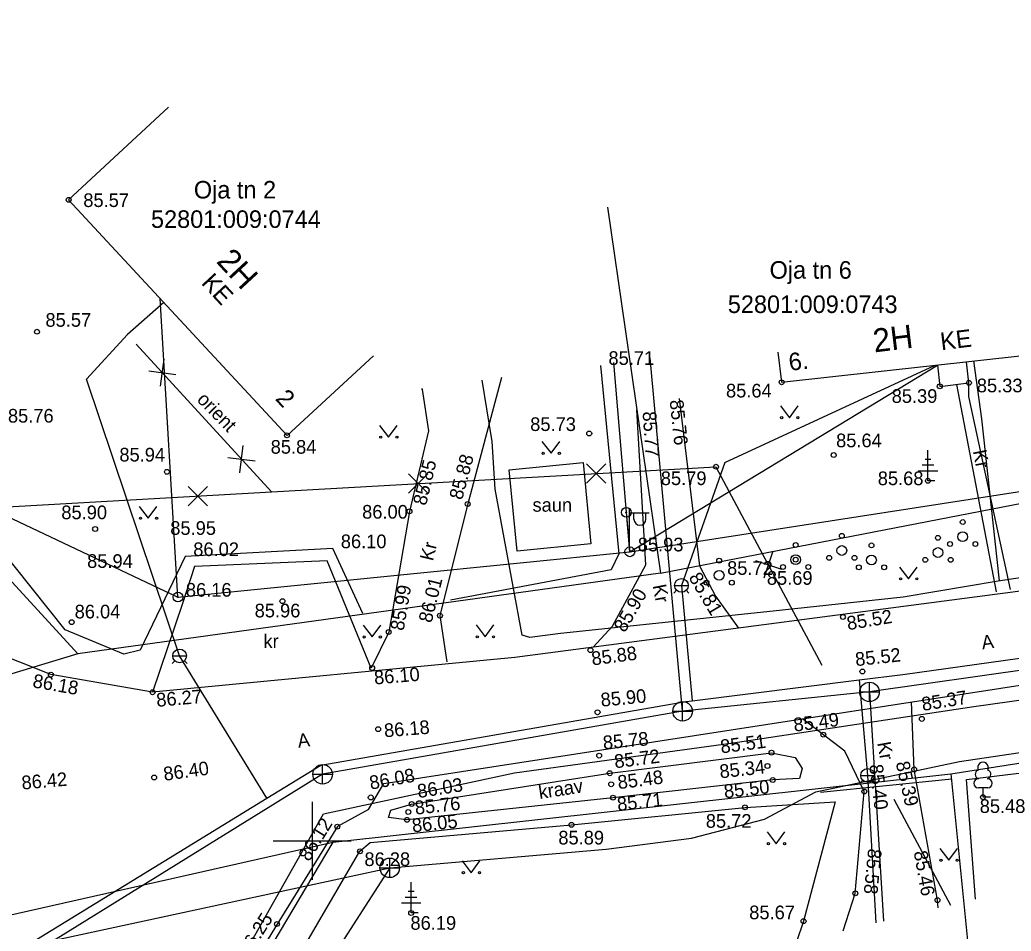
# Model space of a CAD drawing. Extents: x 648748 to 649126, y 6457789 to 6458252.
# Drawn here: x 648985 to 649035.8, y 6458145.4 to 6458192.1 of the extents above; entities that cross this region are included whole.
import ezdxf

# ---------------------------------------------------------------- set-up
doc = ezdxf.new("R2010")
doc.units = 0
for name, color, linetype in [('DTRASS', 7, 'Continuous'), ('HALJASTUS', 7, 'Continuous'), ('HOONE', 7, 'Continuous'), ('KKAEV', 7, 'Continuous'), ('KORGUS-EH2000', 7, 'Continuous'), ('KTRASS', 7, 'Continuous'), ('MPOHULIIN', 7, 'Continuous'), ('PIIR', 7, 'Continuous'), ('POST', 7, 'Continuous'), ('PUU', 7, 'Continuous'), ('RAJATIS', 7, 'Continuous'), ('SITRASS', 7, 'Continuous'), ('SKKAEV', 7, 'Continuous'), ('SKTRASS', 7, 'Continuous'), ('TEE', 7, 'Continuous'), ('VEEKOGU', 7, 'Continuous'), ('VKAEV', 7, 'Continuous'), ('VORK', 7, 'Continuous'), ('VTRASS', 7, 'Continuous')]:
    doc.layers.add(name, color=color, linetype=linetype)

msp = doc.modelspace()

# ---------------------------------------------------------------- linework, layer by layer
at = {"layer": 'DTRASS'}
msp.add_line((649026.058, 6458152.495), (649032.785, 6458153.165), dxfattribs=at)
at = {"layer": 'HALJASTUS'}
for p, q in [((649024, 6458172.292), (649024.463, 6458171.685)), ((649024.463, 6458171.685), (649024.909, 6458172.292)), ((649003.448, 6458171.291), (649003.911, 6458170.684)), ((649003.911, 6458170.684), (649004.357, 6458171.291)), ((649011.774, 6458170.467), (649012.237, 6458169.861)), ((649012.237, 6458169.861), (649012.683, 6458170.467)), ((648991.13, 6458167.138), (648991.594, 6458166.531)), ((648991.594, 6458166.531), (648992.039, 6458167.138)), ((649030.094, 6458164.031), (649030.558, 6458163.425)), ((649030.558, 6458163.425), (649031.003, 6458164.031)), ((649002.601, 6458161.053), (649003.064, 6458160.447)), ((649003.064, 6458160.447), (649003.51, 6458161.053)), ((649008.398, 6458161.061), (649008.861, 6458160.455)), ((649008.861, 6458160.455), (649009.307, 6458161.061)), ((649023.317, 6458150.454), (649023.781, 6458149.847)), ((649023.781, 6458149.847), (649024.226, 6458150.454)), ((649032.163, 6458149.605), (649032.627, 6458148.999)), ((649032.627, 6458148.999), (649033.072, 6458149.605)), ((649007.684, 6458148.969), (649008.147, 6458148.362)), ((649008.147, 6458148.362), (649008.593, 6458148.969))]:
    msp.add_line(p, q, dxfattribs=at)
for points in [[(649033.987, 6458147.007), (649033.538, 6458153.135), (649043.314, 6458154.31), (649049.482, 6458155.214)], [(648996.956, 6458140.042), (649002.443, 6458149.457), (649002.965, 6458149.902), (649013.289, 6458150.815), (649022.182, 6458151.711), (649026.81, 6458151.999), (649025.182, 6458145.874), (649024.817, 6458144.814)]]:
    msp.add_lwpolyline(points, dxfattribs=at)
for centre in [(649024.062, 6458171.685), (649024.891, 6458171.685), (649003.51, 6458170.684), (649004.339, 6458170.684), (649011.836, 6458169.861), (649012.665, 6458169.861), (648991.193, 6458166.531), (648992.022, 6458166.531), (649030.157, 6458163.425), (649030.986, 6458163.425), (649002.663, 6458160.447), (649003.492, 6458160.447), (649008.46, 6458160.455), (649009.289, 6458160.455), (649023.38, 6458149.847), (649024.209, 6458149.847), (649032.226, 6458148.999), (649033.055, 6458148.999), (649007.746, 6458148.362), (649008.575, 6458148.362)]:
    msp.add_circle(centre, 0.055, dxfattribs=at)
at = {"layer": 'HOONE'}
for points in [[(648992.634, 6458187.599), (648987.514, 6458182.852), (648998.705, 6458170.78), (649003.141, 6458174.853)], [(649023.87, 6458175.039), (649024.058, 6458173.502), (649041.542, 6458175.437), (649040.739, 6458182.695)], [(649032.042, 6458174.386), (649032.163, 6458173.293), (649033.658, 6458173.473), (649033.539, 6458174.551)]]:
    msp.add_lwpolyline(points, dxfattribs=at)
at = {"layer": 'KKAEV'}
for p, q in [((649028.562, 6458157.125), (649028.562, 6458158.125)), ((649028.062, 6458157.625), (649029.062, 6458157.625)), ((649018.983, 6458156.135), (649018.983, 6458157.135)), ((649018.483, 6458156.635), (649019.483, 6458156.635)), ((649000.53, 6458152.906), (649000.53, 6458153.906)), ((649000.03, 6458153.406), (649001.03, 6458153.406))]:
    msp.add_line(p, q, dxfattribs=at)
for centre in [(649028.562, 6458157.625), (649018.983, 6458156.635), (649000.53, 6458153.406)]:
    msp.add_circle(centre, 0.5, dxfattribs=at)
at = {"layer": 'KORGUS-EH2000'}
for centre in [(648987.514, 6458182.852), (648985.889, 6458176.092), (649024.058, 6458173.502), (649032.163, 6458173.293), (649033.658, 6458173.473), (648998.705, 6458170.78), (649014.196, 6458170.877), (649026.725, 6458169.771), (649020.691, 6458169.172), (648992.551, 6458168.912), (649031.556, 6458168.447), (649007.969, 6458167.262), (649004.981, 6458166.883), (648988.869, 6458165.982), (649024.777, 6458164.408), (648998.471, 6458162.282), (649006.543, 6458161.54), (649027.199, 6458161.469), (648987.666, 6458161.205), (649003.917, 6458160.7), (649014.257, 6458159.769), (649003.068, 6458158.855), (648986.6, 6458158.516), (649028.198, 6458158.673), (648991.816, 6458157.612), (649014.623, 6458156.586), (649031.244, 6458156.245), (649003.379, 6458155.722), (649026.193, 6458155.438), (649014.705, 6458154.364), (649023.539, 6458154.512), (649023.335, 6458153.829), (648991.897, 6458153.244), (649015.247, 6458153.46), (649030.851, 6458153.655), (649015.32, 6458152.895), (649023.601, 6458153.116), (649002.998, 6458152.22), (649015.413, 6458152.205), (649028.295, 6458152.521), (649034.38, 6458152.229), (649005.094, 6458151.881), (649022.182, 6458151.711), (649004.921, 6458151.471), (649001.287, 6458150.721), (649004.855, 6458151.069), (649013.289, 6458150.815), (649002.443, 6458149.457), (649027.835, 6458147.302), (649032.048, 6458146.955), (649005.068, 6458146.297), (648998.193, 6458145.731), (649025.182, 6458145.874)]:
    msp.add_circle(centre, 0.125, dxfattribs=at)
at = {"layer": 'KTRASS'}
for p, q in [((649018.983, 6458156.635), (649017.319, 6458174.757)), ((649061.979, 6458162.436), (649028.562, 6458157.625)), ((649028.562, 6458157.625), (649018.983, 6458156.635)), ((649028.562, 6458157.625), (649029.287, 6458145.883)), ((649018.983, 6458156.635), (649000.53, 6458153.406)), ((649000.53, 6458153.406), (648975.244, 6458137.772))]:
    msp.add_line(p, q, dxfattribs=at)
at = {"layer": 'MPOHULIIN'}
for p, q in [((648993.115, 6458162.488), (648992.205, 6458177.791)), ((649016.276, 6458164.81), (649015.453, 6458174.508)), ((649016.276, 6458164.81), (649032.042, 6458174.386))]:
    msp.add_line(p, q, dxfattribs=at)
msp.add_lwpolyline([(648949.064, 6458178.85), (648980.689, 6458168.372), (648993.115, 6458162.488), (649016.276, 6458164.81), (649054.033, 6458170.656), (649094.361, 6458177.194), (649107.677, 6458175.236)], dxfattribs=at)
at = {"layer": 'PIIR'}
for p, q in [((648955.09, 6458195.42), (648987.99, 6458159.58)), ((649015.133, 6458182.478), (649017.85, 6458163.71)), ((649017.85, 6458163.71), (649052.92, 6458170.51)), ((649017.85, 6458163.71), (648987.99, 6458159.58)), ((649032.73, 6458153.43), (649096.35, 6458163.48)), ((648987.99, 6458159.58), (648945.9, 6458146.87)), ((649001.06, 6458149.93), (649032.73, 6458153.43)), ((649032.73, 6458153.43), (649034.45, 6458136.158)), ((648970.31, 6458142.98), (649001.06, 6458149.93)), ((649001.06, 6458149.93), (648978.12, 6458111.43))]:
    msp.add_line(p, q, dxfattribs=at)
at = {"layer": 'POST'}
for p, q in [((649016.263, 6458165.052), (649016.263, 6458167.052)), ((649016.097, 6458166.83), (649016.276, 6458164.81)), ((649016.263, 6458166.802), (649017.263, 6458166.802)), ((649016.49, 6458166.481), (649016.49, 6458166.802)), ((649017.103, 6458166.481), (649017.103, 6458166.802))]:
    msp.add_line(p, q, dxfattribs=at)
for centre, radius in [((649016.097, 6458166.83), 0.25), ((649016.097, 6458166.83), 0.0234), ((649016.276, 6458164.81), 0.25), ((649016.276, 6458164.81), 0.0234), ((648993.115, 6458162.488), 0.25), ((648993.115, 6458162.488), 0.0234)]:
    msp.add_circle(centre, radius, dxfattribs=at)
msp.add_arc((649016.796, 6458166.481), 0.306, 180, 0, dxfattribs=at)
at = {"layer": 'PUU'}
for p, q in [((649031.556, 6458168.447), (649031.556, 6458170.022)), ((649031.856, 6458169.248), (649031.256, 6458169.248)), ((649031.706, 6458169.548), (649031.406, 6458169.548)), ((649032.056, 6458168.947), (649031.056, 6458168.947)), ((649031.916, 6458168.447), (649031.556, 6458168.447)), ((649034.62, 6458152.704), (649034.14, 6458152.704)), ((649034.38, 6458152.229), (649034.38, 6458152.704)), ((649034.76, 6458152.229), (649034.38, 6458152.229)), ((649005.068, 6458146.297), (649005.068, 6458147.872)), ((649005.218, 6458147.397), (649004.918, 6458147.397)), ((649005.568, 6458146.797), (649004.568, 6458146.797)), ((649005.368, 6458147.097), (649004.768, 6458147.097)), ((649005.428, 6458146.297), (649005.068, 6458146.297))]:
    msp.add_line(p, q, dxfattribs=at)
for points in [[(649014.775, 6458174.368), (649015.706, 6458164.701), (649015.321, 6458163.893), (649007.084, 6458162.33)], [(649002.59, 6458161.656), (649001.056, 6458164.973), (648993.494, 6458164.57), (648991.171, 6458159.775), (648990.345, 6458159.559), (648987.328, 6458160.816), (648981.354, 6458168.296)]]:
    msp.add_lwpolyline(points, dxfattribs=at)
for centre, radius in [((649033.34, 6458166.336), 0.125), ((649027.141, 6458165.628), 0.125), ((649032.069, 6458165.525), 0.125), ((649033.34, 6458165.586), 0.25), ((649024.777, 6458165.158), 0.125), ((649027.141, 6458164.878), 0.25), ((649028.663, 6458165.139), 0.125), ((649032.069, 6458164.775), 0.25), ((649032.69, 6458165.211), 0.125), ((649033.99, 6458165.211), 0.125), ((649020.855, 6458164.355), 0.125), ((649024.777, 6458164.408), 0.25), ((649026.491, 6458164.503), 0.125), ((649027.791, 6458164.503), 0.125), ((649028.663, 6458164.389), 0.25), ((649031.419, 6458164.4), 0.125), ((649032.719, 6458164.4), 0.125), ((649024.127, 6458164.033), 0.125), ((649025.427, 6458164.033), 0.125), ((649028.013, 6458164.014), 0.125), ((649029.313, 6458164.014), 0.125), ((649020.855, 6458163.605), 0.25), ((649020.205, 6458163.23), 0.125), ((649021.505, 6458163.23), 0.125)]:
    msp.add_circle(centre, radius, dxfattribs=at)
for centre, radius, start, end in [((649034.38, 6458153.749), 0.277, 332.58, 207.42), ((649034.209, 6458153.402), 0.233, 109.022, 253.142), ((649034.55, 6458153.402), 0.233, 286.851, 70.986), ((649034.142, 6458152.942), 0.238, 90.002, 269.395), ((649034.617, 6458152.942), 0.238, 270.605, 89.998)]:
    msp.add_arc(centre, radius, start, end, dxfattribs=at)
at = {"layer": 'RAJATIS'}
msp.add_lwpolyline([(649013.879, 6458169.385), (649014.284, 6458165.219), (649010.503, 6458164.851), (649010.098, 6458169.017), (649013.879, 6458169.385)], dxfattribs=at)
at = {"layer": 'SITRASS'}
for points in [[(649033.891, 6458174.596), (649034.294, 6458171.62), (649035.211, 6458163.32)], [(649050.779, 6458151.372), (649050.885, 6458151.848), (649050.846, 6458155.528), (649051.201, 6458159.4), (649049.722, 6458165.515), (649049.686, 6458165.487), (649035.158, 6458163.312), (649030.285, 6458162.491), (649023.632, 6458161.77), (649012.724, 6458160.616), (649011.154, 6458160.421), (649010.75, 6458160.531), (649009.382, 6458168.026), (649009.225, 6458170.467), (649008.715, 6458173.607)], [(648995.643, 6458121.195), (648992.459, 6458125.184), (648989.418, 6458128.665), (648988.834, 6458130.069), (648992.568, 6458137.175), (649000.571, 6458151.371), (649010.371, 6458153.481), (649021.569, 6458155.012), (649033.911, 6458156.878), (649048.154, 6458158.873), (649059.027, 6458160.391), (649071.774, 6458161.431), (649085.639, 6458163.321), (649085.929, 6458161.874)]]:
    msp.add_lwpolyline(points, dxfattribs=at)
at = {"layer": 'SKKAEV'}
for p, q in [((649003.97, 6458148.11), (649003.97, 6458149.11)), ((649003.47, 6458148.61), (649004.47, 6458148.61))]:
    msp.add_line(p, q, dxfattribs=at)
msp.add_circle((649003.97, 6458148.61), 0.5, dxfattribs=at)
at = {"layer": 'SKTRASS'}
for points in [[(649003.97, 6458148.61), (649015.069, 6458149.564), (649019.431, 6458150.139), (649023.183, 6458151.111), (649025.815, 6458152.505), (649033.168, 6458154.063), (649043.179, 6458155.542), (649052.834, 6458156.983), (649065.23, 6458159.005), (649081.287, 6458162.038), (649091.624, 6458163.937), (649099.708, 6458164.95)], [(648947.113, 6458135.218), (648950.496, 6458136.157), (648962.487, 6458139.467), (648972.91, 6458141.909), (649003.97, 6458148.61)], [(649003.97, 6458148.61), (648998.226, 6458139.651)]]:
    msp.add_lwpolyline(points, dxfattribs=at)
at = {"layer": 'TEE'}
for points in [[(649107.397, 6458177.046), (649100.717, 6458173.988), (649091.348, 6458171.54), (649080.638, 6458169.649), (649068.509, 6458167.394), (649058.16, 6458165.62), (649053.786, 6458164.971), (649038.247, 6458163.046), (649010.385, 6458159.395), (648991.816, 6458157.612), (648986.6, 6458158.516), (648983.403, 6458159.789), (648978.499, 6458164.674), (648956.171, 6458189.218), (648949.185, 6458196.386), (648941.448, 6458204.958), (648937.194, 6458209.825), (648934.521, 6458215.407), (648934.235, 6458222.731), (648937.629, 6458230.732), (648939.834, 6458235.213)], [(649009.706, 6458173.74), (649007.969, 6458167.262), (649006.543, 6458161.54), (649006.829, 6458159.623), (649006.897, 6458159.168)], [(649005.593, 6458173.19), (649005.638, 6458173.136), (649005.958, 6458171.01), (649004.981, 6458166.883), (649003.917, 6458160.7), (649003.021, 6458158.851)], [(649033.018, 6458173.396), (649035.056, 6458162.761)], [(649035.792, 6458162.882), (649033.645, 6458172.77), (649033.658, 6458173.473)], [(649018.812, 6458172.675), (649019.847, 6458164.09), (649020.662, 6458162.532), (649021.843, 6458160.896)], [(649002.881, 6458151.593), (649003.675, 6458152.941), (649070.906, 6458163.327), (649079.075, 6458164.441), (649081.585, 6458165.323), (649092.488, 6458167.317), (649101.716, 6458170.032), (649108.096, 6458172.531)], [(649014.395, 6458159.92), (649015.383, 6458161.002), (649017.103, 6458164.148), (649016.639, 6458172.09)], [(649003.021, 6458158.851), (649000.767, 6458164.354), (648993.963, 6458164.051), (648993.357, 6458162.163), (648991.816, 6458157.612)], [(649032.088, 6458146.553), (649032.048, 6458146.955), (649030.851, 6458153.655), (649030.715, 6458157.118)], [(649027.214, 6458145.388), (649027.835, 6458147.302), (649028.295, 6458152.521), (649027.289, 6458154.599), (649025.126, 6458156.255)], [(649002.881, 6458151.593), (649001.287, 6458150.721), (648998.193, 6458145.731), (648995.296, 6458140.982), (648997.086, 6458139.766), (648997.79, 6458139.425)]]:
    msp.add_lwpolyline(points, dxfattribs=at)
at = {"layer": 'VEEKOGU'}
msp.add_lwpolyline([(649005.094, 6458151.881), (649015.247, 6458153.46), (649023.539, 6458154.512), (649024.756, 6458154.263), (649025.118, 6458153.708), (649024.967, 6458153.185), (649023.601, 6458153.116), (649015.413, 6458152.205), (649004.855, 6458151.069), (649003.903, 6458151.188), (649004.033, 6458151.575), (649005.094, 6458151.881)], dxfattribs=at)
at = {"layer": 'VKAEV'}
for p, q in [((649018.571, 6458163.085), (649019.271, 6458163.085)), ((649018.674, 6458162.838), (649018.534, 6458162.698)), ((649019.169, 6458162.838), (649019.308, 6458162.698)), ((648992.849, 6458159.477), (648993.549, 6458159.477)), ((648992.952, 6458159.23), (648992.812, 6458159.09)), ((648993.447, 6458159.23), (648993.586, 6458159.09)), ((649028.113, 6458153.347), (649028.813, 6458153.347)), ((649028.216, 6458153.1), (649028.076, 6458152.96)), ((649028.711, 6458153.1), (649028.85, 6458152.96))]:
    msp.add_line(p, q, dxfattribs=at)
for centre in [(649018.921, 6458163.085), (648993.199, 6458159.477), (649028.463, 6458153.347)]:
    msp.add_circle(centre, 0.35, dxfattribs=at)
at = {"layer": 'VORK'}
for p, q in [((649000, 6458152), (649000, 6458148)), ((648998, 6458150), (649002, 6458150))]:
    msp.add_line(p, q, dxfattribs=at)
at = {"layer": 'VTRASS'}
for p, q in [((648992.225, 6458173.301), (648992.406, 6458174.69)), ((649021.144, 6458169.382), (649031.894, 6458174.369)), ((648991.621, 6458174.086), (648993.01, 6458173.905)), ((648996.281, 6458168.864), (648996.462, 6458170.253)), ((648995.678, 6458169.649), (648997.066, 6458169.468)), ((649014.057, 6458169.319), (649015.047, 6458168.329)), ((649014.057, 6458168.329), (649015.047, 6458169.319)), ((649020.691, 6458169.172), (649026.126, 6458159.007)), ((649004.941, 6458168.804), (649005.931, 6458167.814)), ((649004.941, 6458167.814), (649005.931, 6458168.804)), ((648993.639, 6458168.164), (648994.629, 6458167.174)), ((648993.639, 6458167.174), (648994.629, 6458168.164)), ((649023.159, 6458163.477), (649023.601, 6458164.806)), ((649022.716, 6458164.363), (649024.045, 6458163.921)), ((649029.8, 6458152.135), (649032.706, 6458146.701))]:
    msp.add_line(p, q, dxfattribs=at)
for points in [[(648904.231, 6458212.879), (648940.565, 6458193.977), (648965.109, 6458166.027), (648997.904, 6458167.882), (649020.691, 6458169.172)], [(648992.393, 6458177.589), (648990.522, 6458175.958)], [(648997.673, 6458152.175), (648993.199, 6458159.477), (648988.435, 6458173.654), (648990.522, 6458175.958)], [(648990.981, 6458175.456), (648997.904, 6458167.882)], [(649021.144, 6458169.382), (649018.921, 6458163.085), (649019.466, 6458157.178)], [(648976.302, 6458139.082), (648997.673, 6458152.175), (649000.44, 6458153.871), (649019.143, 6458157.138), (649019.466, 6458157.178), (649028.03, 6458158.241), (649030.273, 6458158.52), (649062.346, 6458163.005)], [(649028.03, 6458158.241), (649028.463, 6458153.347), (649028.886, 6458145.787)]]:
    msp.add_lwpolyline(points, dxfattribs=at)

# ---------------------------------------------------------------- texts
at = {"layer": 'HOONE'}
for s, height, rotation, p in [('2H', 1.2, 312.8319, (648995.038, 6458179.671)), ('KE', 0.9, 312.8319, (648994.273, 6458178.567)), ('2H', 1.2, 6.9664, (649028.812, 6458175.029)), ('KE', 0.9, 6.9664, (649032.244, 6458175.142)), ('6.', 0.9, 6.9664, (649024.473, 6458174.084)), ('2', 0.9, 312.8319, (648998.071, 6458172.63))]:
    msp.add_text(s, height=height, rotation=rotation, dxfattribs=at).set_placement(p)
at = {"layer": 'KORGUS-EH2000'}
for s, p in [('85.57', (648988.264, 6458182.486)), ('85.57', (648986.325, 6458176.347)), ('85.71', (649015.182, 6458174.391)), ('85.33', (649034.063, 6458172.987)), ('85.64', (649021.206, 6458172.722)), ('85.39', (649029.698, 6458172.446)), ('85.76', (648984.402, 6458171.434)), ('85.73', (649011.171, 6458171.004)), ('85.64', (649026.849, 6458170.17)), ('85.94', (648990.113, 6458169.44)), ('85.84', (648997.868, 6458169.84)), ('85.79', (649017.865, 6458168.231)), ('85.68', (649028.985, 6458168.228)), ('85.90', (648987.138, 6458166.483)), ('86.00', (649002.556, 6458166.511)), ('85.95', (648992.722, 6458165.68)), ('86.10', (649001.463, 6458164.996)), ('85.93', (649016.683, 6458164.833)), ('86.02', (648993.901, 6458164.593)), ('85.94', (648988.46, 6458163.986)), ('85.72', (649021.262, 6458163.628)), ('85.69', (649023.3, 6458163.12)), ('86.16', (648993.522, 6458162.511)), ('86.04', (648987.821, 6458161.397)), ('85.96', (648997.047, 6458161.449)), ('85.48', (649034.21, 6458151.423)), ('85.72', (649020.171, 6458150.664)), ('85.89', (649012.613, 6458149.808)), ('86.28', (649002.674, 6458148.704)), ('85.67', (649022.397, 6458145.975)), ('86.19', (649005.032, 6458145.436))]:
    msp.add_text(s, height=0.7, dxfattribs=at).set_placement(p)
for s, rotation, p in [('85.76', 276.0312, (649018.318, 6458172.572)), ('85.77', 274.0304, (649016.929, 6458171.988)), ('85.88', 74.9886, (649007.68, 6458167.436)), ('85.85', 76.6751, (649005.832, 6458167.15)), ('85.81', 300.5249, (649019.272, 6458163.498)), ('85.99', 80.2366, (649004.683, 6458160.735)), ('86.01', 76.0036, (649006.113, 6458161.133)), ('85.90', 60.1056, (649016.02, 6458160.632)), ('85.52', 9.3399, (649027.457, 6458160.793)), ('85.88', 7.4826, (649014.356, 6458158.983)), ('85.52', 6.1001, (649027.864, 6458158.947)), ('86.10', 4.6681, (649003.196, 6458158.01)), ('86.18', 350.1697, (648985.635, 6458157.869)), ('86.27', 4.8037, (648992.035, 6458156.863)), ('85.90', 5.3382, (649014.814, 6458156.87)), ('85.37', 9.2374, (649031.29, 6458156.649)), ('85.49', 7.1694, (649024.708, 6458155.591)), ('86.18', 4.6681, (649003.707, 6458155.299)), ('85.78', 5.3382, (649014.929, 6458154.678)), ('85.51', 7.2323, (649020.961, 6458154.475)), ('85.72', 7.2323, (649015.524, 6458153.711)), ('86.40', 7.8661, (648992.42, 6458153.07)), ('85.34', 6.3519, (649020.912, 6458153.197)), ('85.40', 277.0284, (649028.544, 6458153.88)), ('85.39', 282.4143, (649029.904, 6458153.996)), ('86.42', 4.8884, (648985.128, 6458152.622)), ('86.08', 10.381, (649002.998, 6458152.615)), ('85.48', 7.2323, (649015.694, 6458152.64)), ('86.03', 8.8356, (649005.44, 6458152.185)), ('85.50', 6.3519, (649021.138, 6458152.178)), ('85.76', 6.141, (649005.29, 6458151.336)), ('85.71', 6.3519, (649015.663, 6458151.521)), ('86.05', 6.141, (649005.147, 6458150.422)), ('86.12', 58.1965, (648999.835, 6458148.894)), ('85.58', 264.3363, (649028.497, 6458149.624)), ('85.46', 280.1219, (649030.824, 6458149.426)), ('86.25', 57.6746, (648996.761, 6458144.03))]:
    msp.add_text(s, height=0.7, rotation=rotation, dxfattribs=at).set_placement(p)
at = {"layer": 'PIIR'}
for s, rotation, p in [('Oja tn 2', 360, (648993.931, 6458182.923)), ('52801:009:0744', 360, (648991.734, 6458181.415)), ('Oja tn 6', 0, (649023.439, 6458178.811)), ('52801:009:0743', 0, (649021.299, 6458177.053))]:
    msp.add_text(s, height=0.9, rotation=rotation, dxfattribs=at).set_placement(p)
at = {"layer": 'RAJATIS'}
msp.add_text('saun', height=0.7, dxfattribs=at).set_placement((649011.289, 6458166.866))
at = {"layer": 'TEE'}
for s, rotation, p in [('Kr', 280.8499, (649033.856, 6458169.976)), ('Kr', 76.3831, (649006.186, 6458164.305)), ('Kr', 280.8499, (649017.441, 6458163.079)), ('A', 7.0493, (649034.347, 6458159.809)), ('A', 7.0493, (648999.289, 6458154.767)), ('Kr', 280.3495, (649028.952, 6458155.014))]:
    msp.add_text(s, height=0.7, rotation=rotation, dxfattribs=at).set_placement(p)
msp.add_text('kr', height=0.7, dxfattribs=at).set_placement((648997.498, 6458159.878))
at = {"layer": 'VEEKOGU'}
msp.add_text('kraav', height=0.7, rotation=8.8356, dxfattribs=at).set_placement((649011.655, 6458152.133))
at = {"layer": 'VTRASS'}
msp.add_text('orient', height=0.7, rotation=314.3772, dxfattribs=at).set_placement((648994.046, 6458172.572))

doc.saveas('drawing.dxf')
